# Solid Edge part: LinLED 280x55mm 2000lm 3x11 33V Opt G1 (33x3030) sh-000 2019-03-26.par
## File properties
Author: radoslaw.kuczynski
Template: iso metric part.par
Last saved by: radoslaw.kuczynski
Revision: 1
Application: Solid Edge
Gęstość: 0,000 kg/m^3
Dokładność: 0,990
Username: radoslaw.kuczynski
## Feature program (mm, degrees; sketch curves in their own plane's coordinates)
body "unnamed Body 1"
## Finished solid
Body 1: solid body, 1063 faces, 2660 edges, 1662 vertices.
  Faces by surface: plane 560, cylinder 229, spline 160, cone 40, torus 22, sphere 20, swept 18, spun 14
  Edges by curve: line 1588, curve on surface 592, circle 284, ellipse 120, spline 64, intersection 12
Bounding box of the edges (mm; curved faces can reach further): 280.000 x 5.000 x 55.000, from (-140, -5, -27.5) to (140, 0, 27.5).
Cylindrical faces by radius (mm): R0.2 x86, R0.2002 x4, R0.2169 x6, R0.25 x16, R0.3 x4, R0.3373 x6, R0.4 x16, R0.4006 x4, R0.4008 x4, R0.525 x4, R0.6 x16, R0.75 x9, R1 x14, R1.0894 x4, R1.1 x28, R2.375 x8
Conical faces (half-angle, radius in mm at the cone's reference point): 0.5 deg R0.5056 x8, 0.5 deg R1.0082 x8, 1 deg R0.5511 x4, 10 deg R0.2132 x4, 10 deg R0.4132 x4, 18.4844 deg R1.0657 x8, 27.363 deg R0.6214 x4
Toroidal faces (ring radius, tube radius in mm): R0.1 r0.2 x2, R0.8 r0.2 x8, R0.8522 r0.3 x4, R0.9002 r0.2 x2, R0.9018 r0.2 x2, R1.3 r0.2 x4
Spherical faces by radius (mm): R0.2 x16, R0.6 x4
Planar faces by outward normal: +x 79, +y 13, +z 73, -x 79, -y 87, -z 75, oblique 154
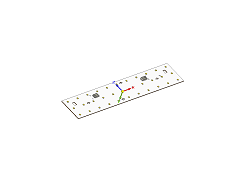
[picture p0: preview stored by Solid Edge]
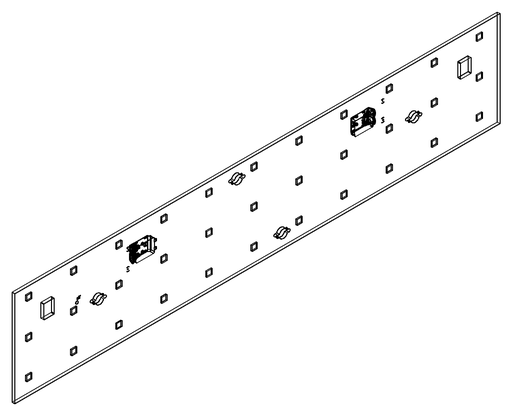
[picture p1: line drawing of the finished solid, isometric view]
